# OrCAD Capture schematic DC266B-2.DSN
size Custom
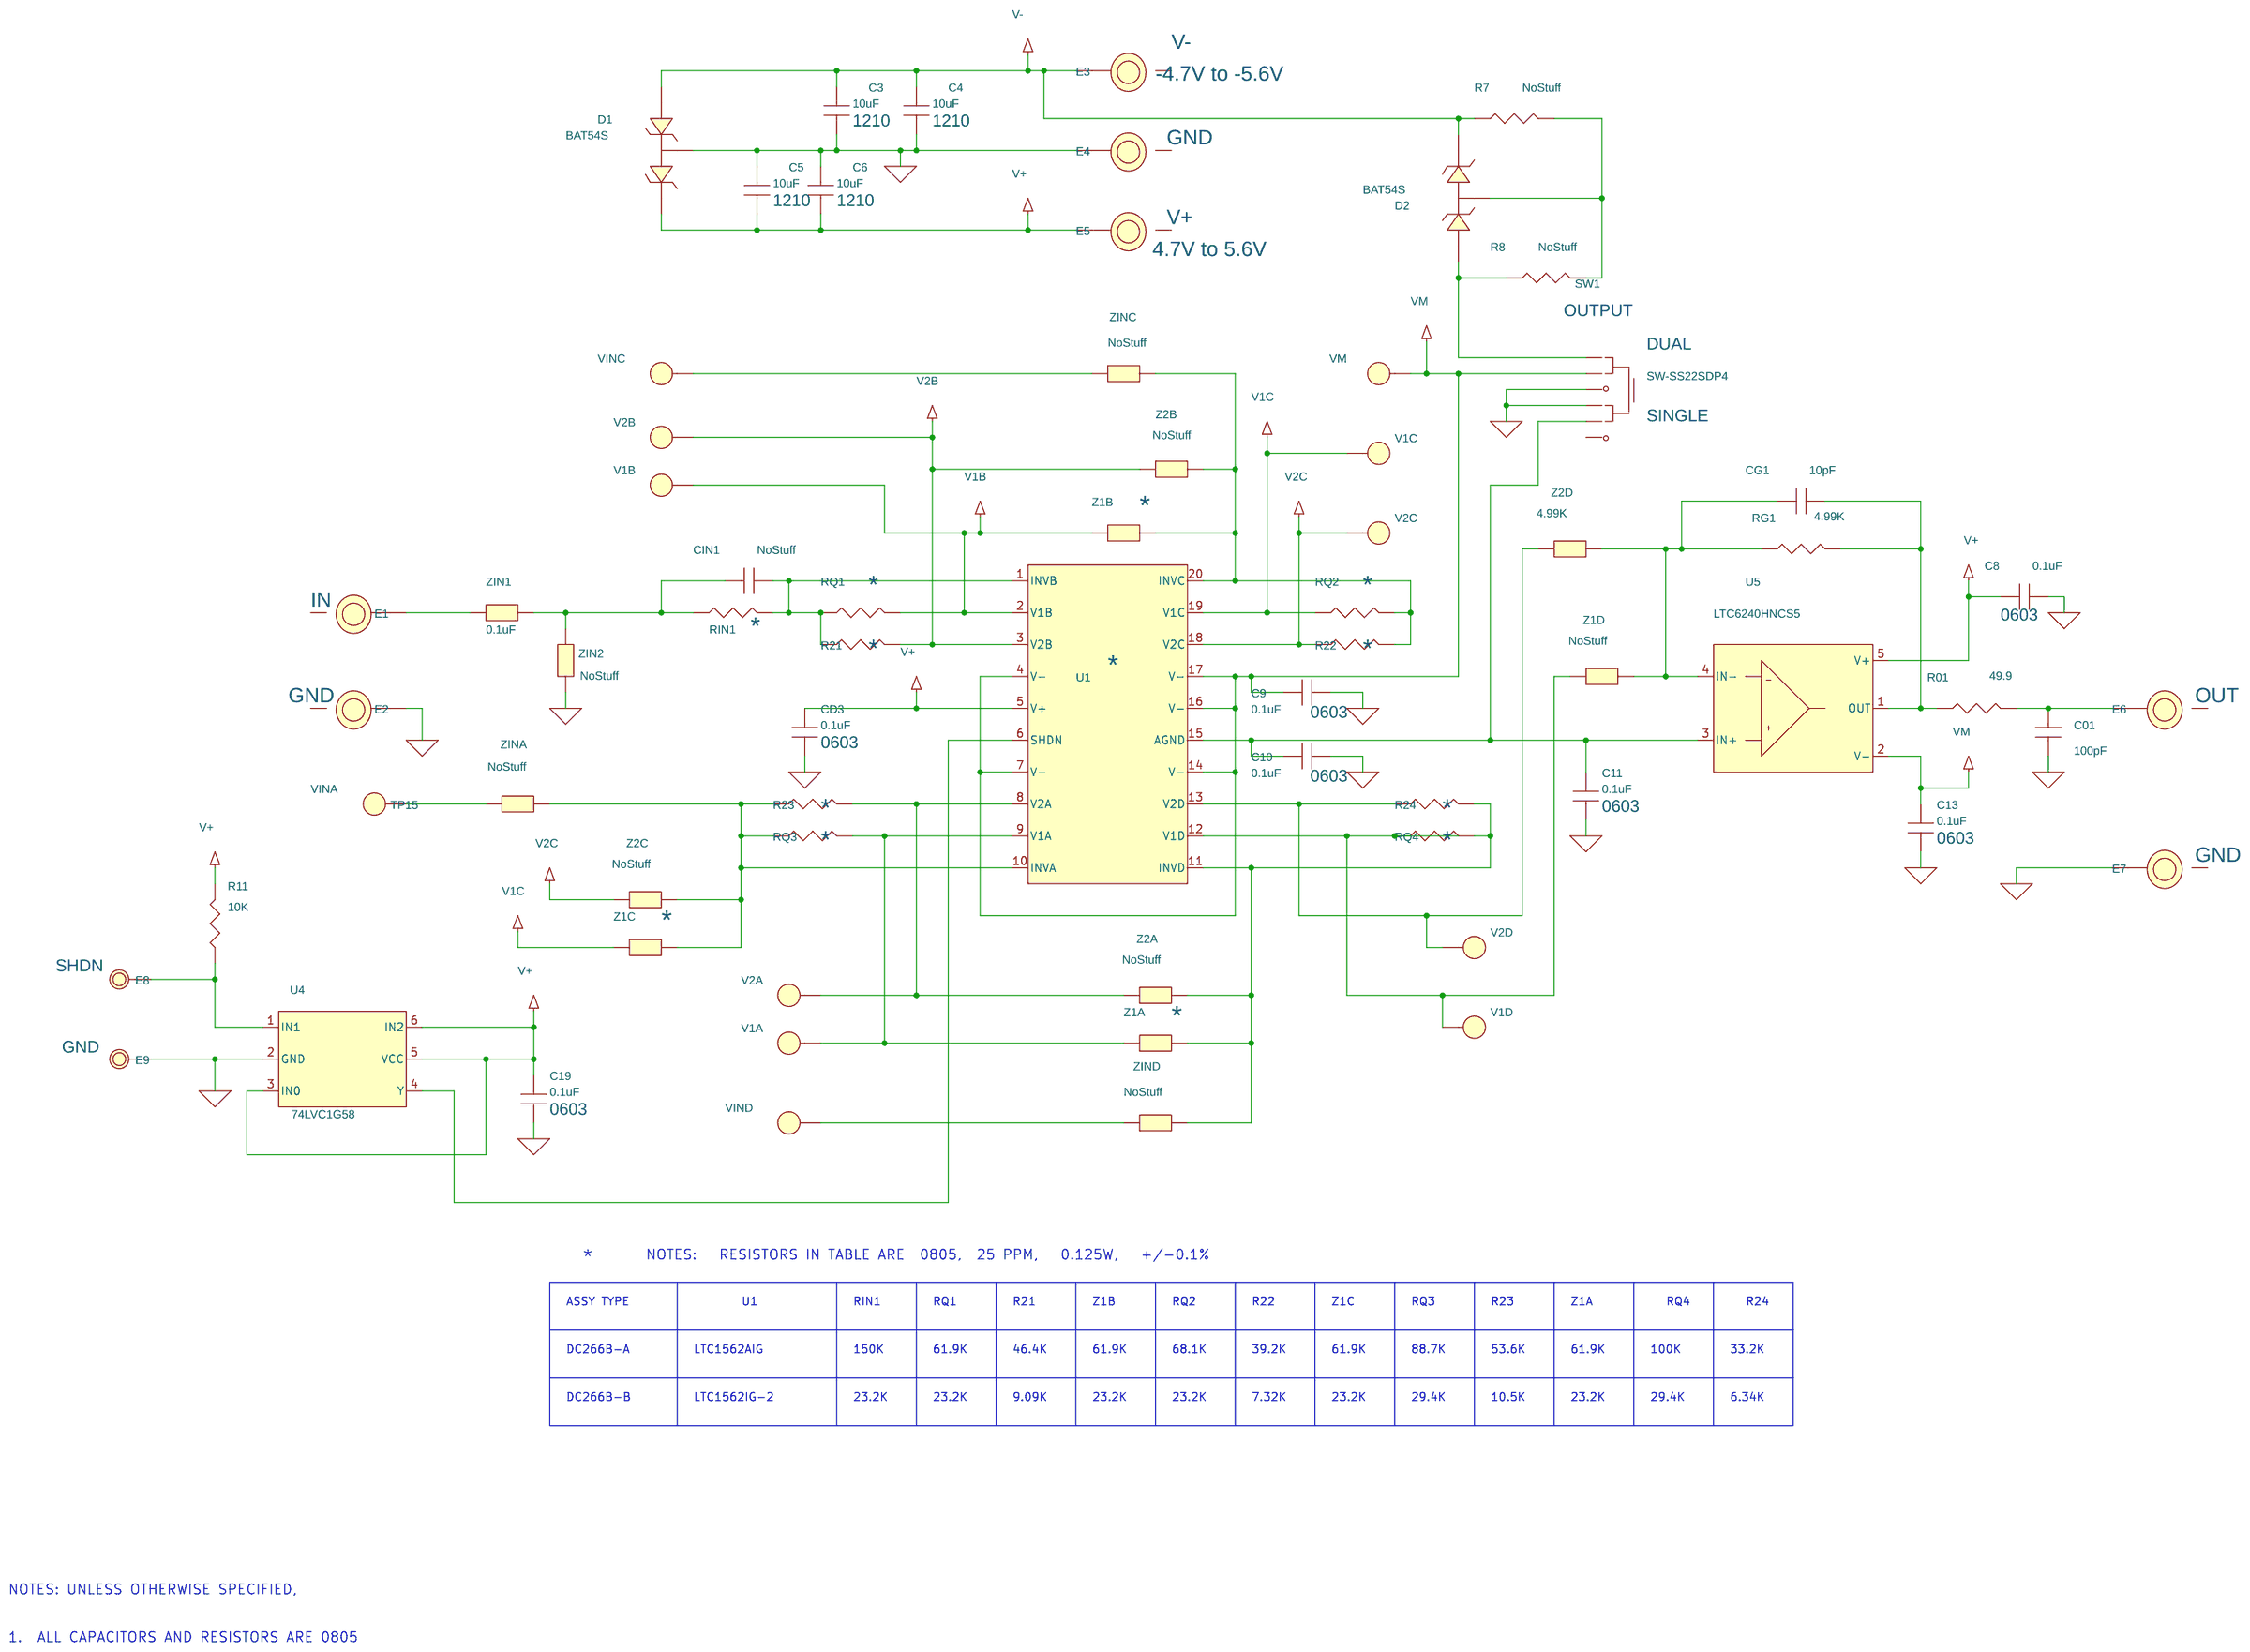
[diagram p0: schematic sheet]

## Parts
C01  100pF  [0805]
C3  10uF  [1210]
C4  10uF  [1210]
C5  10uF  [1210]
C6  10uF  [1210]
C8  0.1uF  [0603]
C9  0.1uF  [0603]
C10  0.1uF  [0603]
C11  0.1uF  [0603]
C13  0.1uF  [0603]
C19  0.1uF  [0603]
CD3  0.1uF  [0603]
CG1  10pF  [0805]
CIN1  NoStuff  [0805]
D1  BAT54S  [SOT23]
D2  BAT54S  [SOT23]
E1  IN  [MM/2501]
E2  GND  [MM/2501]
E3  V-  [MM/2501]
E4  GND  [MM/2501]
E5  V+  [MM/2501]
E6  OUT  [MM/2501]
E7  GND  [MM/2501]
E8  MILL-MAX 2308  [MILLMAX2308]
E9  MILL-MAX 2308  [MILLMAX2308]
R01  49.9  [0805]
R7  NoStuff  [0805]
R8  NoStuff  [0805]
R11  10K  [0805]
R21  *  [0805]
R22  *  [0805]
R23  *  [0805]
R24  *  [0805]
RG1  4.99K  [0805]
RIN1  *  [0805]
RQ1  *  [0805]
RQ2  *  [0805]
RQ3  *  [0805]
RQ4  *  [0805]
SW1  SW-SS22SDP4  [SW-SS22S]
TP1  VINC  [HOLE-35X50]
TP2  V2B  [HOLE-35X50]
TP3  V1B  [HOLE-35X50]
TP5  VM  [HOLE-35X50]
TP6  V1C  [HOLE-35X50]
TP7  V2C  [HOLE-35X50]
TP8  V2A  [HOLE-35X50]
TP9  V1A  [HOLE-35X50]
TP10  VIND  [HOLE-35X50]
TP11  V2D  [HOLE-35X50]
TP12  V1D  [HOLE-35X50]
TP15  VINA  [HOLE-35X50]
U1  *  [SSOP-20]
U4  74LVC1G58  [SOT363]
U5  LTC6240HNCS5  [5PINTSOT23]
Z1A  *  [0805]
Z1B  *  [0805]
Z1C  *  [0805]
Z1D  NoStuff  [0805]
Z2A  NoStuff  [0805]
Z2B  NoStuff  [0805]
Z2C  NoStuff  [0805]
Z2D  4.99K  [0805]
ZIN1  0.1uF  [0805]
ZIN2  NoStuff  [0805]
ZINA  NoStuff  [0805]
ZINC  NoStuff  [0805]
ZIND  NoStuff  [0805]

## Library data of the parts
C01 CG1 CIN1 = CAP0603
C3-C6 = 10uF_25V_10%_X5R_1210: CAP., 10uF, X7R, 16V, 10%, 1210; DIELECTRIC: X7R; Part Number: AVX, 1210YC106KAT2A
C8 C10 CD3 = 0.1uF_16V_10%_X7R_0603: Part Number: AVX 0603YC104KAT2 / D
C9 C19 = 0.1uF_16V_10%_X7R_0603: Part Number: AVX 0603YC104KAT2
C11 = 0.1uF_16V_10%_X7R_0603: Part Number: AVX 0603YC104KAT2 / AVX 0603YC104KAT2
C13 = 0.1uF_16V_10%_X7R_0603: Part Number: AVX 0603YC104KAT2 / AVX 0805YC104KAT2
D1 D2 = BAT54STA_1
E1 = E_13: VOLTAGE: ????
E2 = E_13: VOLTAGE: 1
E3 = E_13: VOLTAGE: -4.7V to -5.6V
E4 = E_13: VOLTAGE: (4.7V to 5.6V)
E5 = E_13: VOLTAGE: 4.7V to 5.6V
E6 E7 = E_13: VOLTAGE: 2.7V-5.5V
E8 = TURRET,_064_MTG_HOLE: 1: SHDN
E9 = TURRET,_064_MTG_HOLE: 1: GND
R01 R11 R21-R24 RG1 RIN1 RQ1-RQ4 = AAC-0805
R7 R8 = OPT_0805
SW1 = SW-SS22SDP4_1: 1 COLUMN: OUTPUT; 2 COLUMN: DUAL; 3 COLUMN: SINGLE
TP1-TP3 TP5-TP12 TP15 = TURRETL_1: TURRET; Part Number: MILL MAX 2501
U1 = LTC1562-2_0
U4 = 74LVC1G58
U5 = LTC6240HNCS5
Z1A Z1B Z1C Z1D Z2A Z2B Z2C Z2D ZIN1 ZIN2 ZINA ZINC ZIND = AAC-0805_1

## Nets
GND: C01.1 C3.2 C4.2 C5.1 C6.1 C8.1 C9.2 C10.2 C11.1 C13.1 C19.1 CD3.1 D1.3 E2.1(A) E4.1(A) E7.1(A) E9.1(A) SW1.3 SW1.4 U4.2(GND) ZIN2.2
V1B: RQ1.2 TP3.1(TP) U1.2(V1B) Z1B.1
V1C: RQ2.1 TP6.1(TP) U1.19(V1C) Z1C.1
V2B: R21.2 TP2.1(TP) U1.3(V2B) Z2B.1
V2C: R22.1 TP7.1(TP) U1.18(V2C) Z2C.1
V+: C5.2 C6.2 C8.2 C19.2 CD3.2 D1.2 E5.1(A) R11.2 U1.5(V+) U4.3(IN0) U4.5(VCC) U4.6(IN2) U5.5(V+)
V-: C3.1 C4.1 D1.1 D2.2 E3.1(A) R7.1
VM: C9.1 C13.2 SW1.2 TP5.1(TP) U1.4(V-) U1.7(V-) U1.14(V-) U1.16(V-) U1.17(V-) U5.2(V-)
N00141: CIN1.2 R21.1 RIN1.2 RQ1.1 U1.1(INVB)
N176480: CIN1.1 RIN1.1 ZIN1.2 ZIN2.1
N16892911: R22.2 RQ2.2 U1.20(INVC) Z1B.2 Z2B.2 ZINC.2
N16900623: TP1.1(TP) ZINC.1
N16960682: E8.1(A) R11.1 U4.1(IN1)
N16967110: U1.6(SHDN) U4.4(Y)
N17006780: D2.1 R8.1 SW1.1
N17007936: D2.3 R7.2 R8.2
N17013964: C10.1 C11.2 SW1.5 U1.15(AGND) U5.3(IN+)
N17024950: CG1.2 R01.1 RG1.2 U5.1(OUT)
N17024966: CG1.1 RG1.1 U5.4(IN-) Z1D.2 Z2D.2
N17036416: R23.2 TP8.1(TP) U1.8(V2A) Z2A.1
N17036720: RQ3.2 TP9.1(TP) U1.9(V1A) Z1A.1
N17037026: R23.1 RQ3.1 U1.10(INVA) Z1C.2 Z2C.2 ZINA.2
N17048121: R24.1 TP11.1(TP) U1.13(V2D) Z2D.1
N17048442: RQ4.1 TP12.1(TP) U1.12(V1D) Z1D.1
N17048765: R24.2 RQ4.2 U1.11(INVD) Z1A.2 Z2A.2 ZIND.2
N17058825: TP10.1(TP) ZIND.1
N17248602: C01.2 E6.1(A) R01.2
N17527328: E1.1(A) ZIN1.1
N17529225: TP15.1(TP) ZINA.1

Not connected (* = marked no-connect by the designer): SW1 6

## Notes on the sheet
- *
- NOTES:   RESISTORS IN TABLE ARE  0805,  25 PPM,   0.125W,   +/-0.1%
- ASSY TYPE
- U1
- RIN1
- RQ1
- R21
- Z1B
- RQ2
- R22
- Z1C
- RQ3
- R23
- Z1A
- RQ4
- R24
- DC266B-A
- LTC1562AIG
- 150K
- 61.9K
- 46.4K
- 61.9K
- 68.1K
- 39.2K
- 61.9K
- 88.7K
- 53.6K
- 61.9K
- 100K
- 33.2K
- DC266B-B
- LTC1562IG-2
- 23.2K
- 23.2K
- 9.09K
- 23.2K
- 23.2K
- 7.32K
- 23.2K
- 29.4K
- 10.5K
- 23.2K
- 29.4K
- 6.34K
- NOTES: UNLESS OTHERWISE SPECIFIED,
- 1.  ALL CAPACITORS AND RESISTORS ARE 0805
